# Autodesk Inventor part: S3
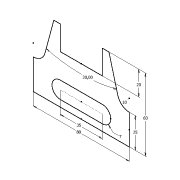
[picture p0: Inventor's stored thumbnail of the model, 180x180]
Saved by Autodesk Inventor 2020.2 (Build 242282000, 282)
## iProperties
Created: 2013-12
Part Number: S3
Material: Ogólny
Document SubType Name: Modeling
Designer: F.Stasiak
Density: 1 g/cm^3
Appearance: Domyślna
Manager: www.cadconsulting.pl
Company: Fabian Stasiak CAD Consulting
Author: F.Stasiak
Subject: Zbiór ćwiczeń. Autodesk Inventor 2020. Kurs podstawowy
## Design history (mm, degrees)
sketch "Szkic1"
  geometry: L1 (-40, 0)-(40, 0); L2 (40, 0)-(40, 25); L3 (30.341, 32.412)-(22.949, 60); L4 (22.949, 60)-(17.5, 60); L5 (17.5, 60)-(17.5, 40); L6 (17.5, 40)-(-17.5, 40); L7 (-17.5, 40)-(-17.5, 60); L8 (-17.5, 60)-(-22.949, 60); L9 (-22.949, 60)-(-30.341, 32.412); L10 (-40, 25)-(-40, 0); L11 (-17.5, 12.5)-(17.5, 12.5); L12 (-17.5, 5.5)-(17.5, 5.5); L13 (17.5, 19.5)-(-17.5, 19.5); A1 r 10 centre (40, 35) between (30.341, 32.412) and (40, 25); A2 r 10 centre (-40, 35) between (-40, 25) and (-30.341, 32.412); A3 r 7 centre (-17.5, 12.5) between (-17.5, 19.5) and (-17.5, 5.5); A4 r 7 centre (17.5, 12.5) between (17.5, 5.5) and (17.5, 19.5); 6 further points
  constraints: 28 end point, 9 point on circle, 6 tangent, 5 parallel, 4 centre point, 4 midpoint, 4 point on line, 2 collinear, 2 equal length, 2 perpendicular, 1 coincident, 1 equal radius, 1 horizontal, 1 horizontal alignment, 1 vertical, 1 vertical alignment
  dimensions: "d0" = 80 distance of L1.start L1.end; "d1" = 35 distance of L11.start L11.end; "d2" = 7 radius of A4; "d3" = 60 distance between parallel lines of L4 L1; "d4" = 20 distance of L4.end L5.end; "d5" = 10 radius of A1; "d6" = 30 deg angle of L3 L9; "d7" = 25 distance of L1.end L2.end
